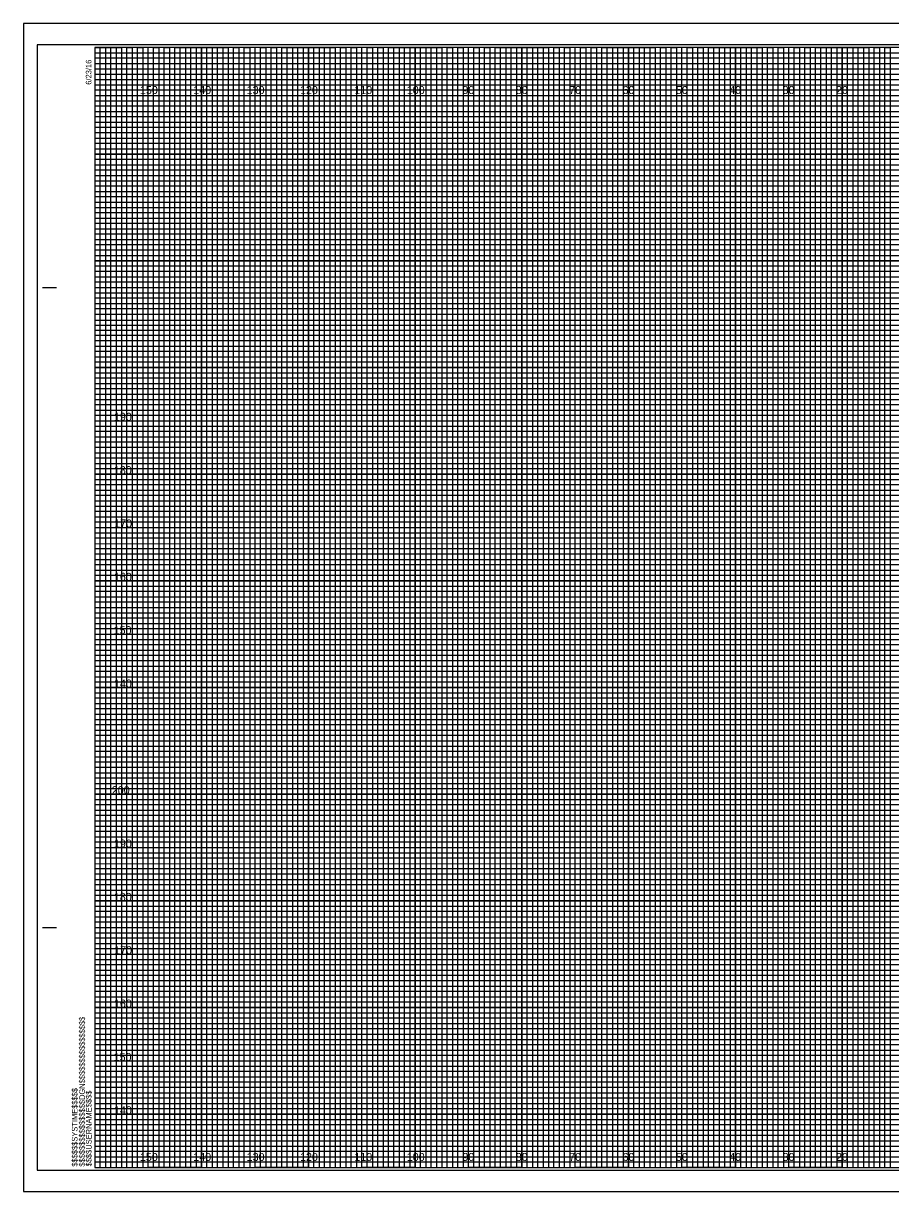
# Model space of a CAD drawing. Extents: x -13 to 323, y -5 to 4174.
# Drawn here: x -13.4 to 149.1, y 215.5 to 434.5 of the extents above; entities that cross this region are included whole.
import ezdxf

# ---------------------------------------------------------------- set-up
doc = ezdxf.new("R2010")
doc.units = 0
for name, color, linetype in [('Exist Cross Section Cell', 7, 'Continuous'), ('Exist XS Center Line Elevation Label', 7, 'Continuous'), ('Exist XS Ground Line', 7, 'Continuous'), ('Prop CMT Guardrail Graphics', 7, 'Continuous'), ('Prop CMT Pvmt Course 1', 7, 'Continuous'), ('Prop CMT Pvmt Course 2', 7, 'Continuous'), ('Prop CMT Pvmt Course 3', 7, 'Continuous'), ('Prop CMT Shld Paved Course 1', 7, 'Continuous'), ('Prop CMT Shld Paved Course 2', 7, 'Continuous'), ('Prop CMT Subgrade Earthwork', 7, 'Continuous'), ('Scratch_Level_0', 7, 'Continuous')]:
    doc.layers.add(name, color=color, linetype=linetype)

msp = doc.modelspace()

# ---------------------------------------------------------------- linework, layer by layer
at = {"layer": 'Exist XS Center Line Elevation Label'}
for points in [[(0, 430), (5, 430), (5, 220), (15, 220), (15, 430), (25, 430), (25, 220), (35, 220), (35, 430), (45, 430), (45, 220), (55, 220), (55, 430), (65, 430), (65, 220), (75, 220), (75, 430), (85, 430), (85, 220), (95, 220), (95, 430), (105, 430), (105, 220), (115, 220), (115, 430), (125, 430), (125, 220), (135, 220), (135, 430), (145, 430), (145, 220), (155, 220)], [(0, 425), (275, 425)], [(0, 405), (320, 405), (320, 415), (0, 415)], [(0, 385), (320, 385), (320, 395), (0, 395)], [(0, 365), (320, 365), (320, 375), (0, 375)], [(0, 345), (320, 345), (320, 355), (0, 355)], [(0, 325), (320, 325), (320, 335), (0, 335)], [(0, 305), (320, 305), (320, 315), (0, 315)], [(0, 285), (320, 285), (320, 295), (0, 295)], [(0, 265), (320, 265), (320, 275), (0, 275)], [(0, 245), (320, 245), (320, 255), (0, 255)], [(0, 225), (320, 225), (320, 235), (0, 235)]]:
    msp.add_lwpolyline(points, dxfattribs=at)
at = {"layer": 'Exist XS Ground Line'}
for p, q in [((10, 430), (0, 430)), ((10, 220), (10, 430)), ((30, 430), (20, 430)), ((20, 430), (20, 220)), ((30, 220), (30, 430)), ((50, 430), (40, 430)), ((40, 430), (40, 220)), ((50, 220), (50, 430)), ((70, 430), (60, 430)), ((60, 430), (60, 220)), ((70, 220), (70, 430)), ((90, 430), (80, 430)), ((80, 430), (80, 220)), ((90, 220), (90, 430)), ((110, 430), (100, 430)), ((100, 430), (100, 220)), ((110, 220), (110, 430)), ((130, 430), (120, 430)), ((120, 430), (120, 220)), ((130, 220), (130, 430)), ((150, 430), (140, 430)), ((140, 430), (140, 220)), ((20, 220), (10, 220)), ((40, 220), (30, 220)), ((60, 220), (50, 220)), ((80, 220), (70, 220)), ((100, 220), (90, 220)), ((120, 220), (110, 220)), ((140, 220), (130, 220))]:
    msp.add_line(p, q, dxfattribs=at)
for points in [[(0, 420), (320, 420), (320, 410), (0, 410)], [(0, 400), (320, 400), (320, 390), (0, 390)], [(0, 380), (320, 380), (320, 370), (0, 370)], [(0, 360), (320, 360), (320, 350), (0, 350)], [(0, 340), (320, 340), (320, 330), (0, 330)], [(0, 320), (320, 320), (320, 310), (0, 310)], [(0, 300), (320, 300), (320, 290), (0, 290)], [(0, 280), (320, 280), (320, 270), (0, 270)], [(0, 260), (320, 260), (320, 250), (0, 250)], [(0, 240), (320, 240), (320, 230), (0, 230)]]:
    msp.add_lwpolyline(points, dxfattribs=at)
at = {"layer": 'Prop CMT Pvmt Course 1'}
for p, q in [((323.3, 434.5), (-13.4, 434.5)), ((-13.4, 434.5), (-13.4, 215.5)), ((-13.4, 215.5), (323.3, 215.5))]:
    msp.add_line(p, q, dxfattribs=at)
at = {"layer": 'Prop CMT Pvmt Course 2'}
msp.add_lwpolyline([(-13.4, 215.5), (323.3, 215.5), (323.3, 434.5), (-13.4, 434.5)], close=True, dxfattribs=at)
at = {"layer": 'Prop CMT Pvmt Course 3'}
msp.add_lwpolyline([(-10.8, 219.5), (322.4, 219.5), (322.4, 430.5), (-10.8, 430.5)], close=True, dxfattribs=at)
at = {"layer": 'Prop CMT Shld Paved Course 1'}
for p, q in [((-9.8, 385), (-7.3, 385)), ((-9.7, 385), (-7.2, 385)), ((-9.8, 265), (-7.3, 265)), ((-9.7, 265), (-7.2, 265)), ((0, 220), (0, 220)), ((0, 220), (0, 220)), ((0, 220), (0, 220)), ((0, 220), (0, 220)), ((0, 220), (0, 220)), ((0, 220), (0, 220)), ((0, 220), (0, 220))]:
    msp.add_line(p, q, dxfattribs=at)
msp.add_lwpolyline([(320, 430), (0, 430), (0, 220), (320, 220)], close=True, dxfattribs=at)
at = {"layer": 'Prop CMT Shld Paved Course 2'}
for points in [[(0, 220), (1, 220), (1, 430), (2, 430), (2, 220)], [(2, 220), (3, 220), (3, 430), (4, 430), (4, 220)], [(5, 220), (6, 220), (6, 430), (7, 430), (7, 220)], [(7, 220), (8, 220), (8, 430), (9, 430), (9, 220)], [(10, 220), (11, 220), (11, 430), (12, 430), (12, 220)], [(12, 220), (13, 220), (13, 430), (14, 430), (14, 220)], [(15, 220), (16, 220), (16, 430), (17, 430), (17, 220)], [(17, 220), (18, 220), (18, 430), (19, 430), (19, 220)], [(20, 220), (21, 220), (21, 430), (22, 430), (22, 220)], [(22, 220), (23, 220), (23, 430), (24, 430), (24, 220)], [(25, 220), (26, 220), (26, 430), (27, 430), (27, 220)], [(27, 220), (28, 220), (28, 430), (29, 430), (29, 220)], [(30, 220), (31, 220), (31, 430), (32, 430), (32, 220)], [(32, 220), (33, 220), (33, 430), (34, 430), (34, 220)], [(35, 220), (36, 220), (36, 430), (37, 430), (37, 220)], [(37, 220), (38, 220), (38, 430), (39, 430), (39, 220)], [(40, 220), (41, 220), (41, 430), (42, 430), (42, 220)], [(42, 220), (43, 220), (43, 430), (44, 430), (44, 220)], [(45, 220), (46, 220), (46, 430), (47, 430), (47, 220)], [(47, 220), (48, 220), (48, 430), (49, 430), (49, 220)], [(50, 220), (51, 220), (51, 430), (52, 430), (52, 220)], [(52, 220), (53, 220), (53, 430), (54, 430), (54, 220)], [(55, 220), (56, 220), (56, 430), (57, 430), (57, 220)], [(57, 220), (58, 220), (58, 430), (59, 430), (59, 220)], [(60, 220), (61, 220), (61, 430), (62, 430), (62, 220)], [(62, 220), (63, 220), (63, 430), (64, 430), (64, 220)], [(65, 220), (66, 220), (66, 430), (67, 430), (67, 220)], [(67, 220), (68, 220), (68, 430), (69, 430), (69, 220)], [(70, 220), (71, 220), (71, 430), (72, 430), (72, 220)], [(72, 220), (73, 220), (73, 430), (74, 430), (74, 220)], [(75, 220), (76, 220), (76, 430), (77, 430), (77, 220)], [(77, 220), (78, 220), (78, 430), (79, 430), (79, 220)], [(80, 220), (81, 220), (81, 430), (82, 430), (82, 220)], [(82, 220), (83, 220), (83, 430), (84, 430), (84, 220)], [(85, 220), (86, 220), (86, 430), (87, 430), (87, 220)], [(87, 220), (88, 220), (88, 430), (89, 430), (89, 220)], [(90, 220), (91, 220), (91, 430), (92, 430), (92, 220)], [(92, 220), (93, 220), (93, 430), (94, 430), (94, 220)], [(95, 220), (96, 220), (96, 430), (97, 430), (97, 220)], [(97, 220), (98, 220), (98, 430), (99, 430), (99, 220)], [(100, 220), (101, 220), (101, 430), (102, 430), (102, 220)], [(102, 220), (103, 220), (103, 430), (104, 430), (104, 220)], [(105, 220), (106, 220), (106, 430), (107, 430), (107, 220)], [(107, 220), (108, 220), (108, 430), (109, 430), (109, 220)], [(110, 220), (111, 220), (111, 430), (112, 430), (112, 220)], [(112, 220), (113, 220), (113, 430), (114, 430), (114, 220)], [(115, 220), (116, 220), (116, 430), (117, 430), (117, 220)], [(117, 220), (118, 220), (118, 430), (119, 430), (119, 220)], [(120, 220), (121, 220), (121, 430), (122, 430), (122, 220)], [(122, 220), (123, 220), (123, 430), (124, 430), (124, 220)], [(125, 220), (126, 220), (126, 430), (127, 430), (127, 220)], [(127, 220), (128, 220), (128, 430), (129, 430), (129, 220)], [(130, 220), (131, 220), (131, 430), (132, 430), (132, 220)], [(132, 220), (133, 220), (133, 430), (134, 430), (134, 220)], [(135, 220), (136, 220), (136, 430), (137, 430), (137, 220)], [(137, 220), (138, 220), (138, 430), (139, 430), (139, 220)], [(140, 220), (141, 220), (141, 430), (142, 430), (142, 220)], [(142, 220), (143, 220), (143, 430), (144, 430), (144, 220)], [(145, 220), (146, 220), (146, 430), (147, 430), (147, 220)], [(147, 220), (148, 220), (148, 430), (149, 430), (149, 220)]]:
    msp.add_lwpolyline(points, dxfattribs=at)
at = {"layer": 'Prop CMT Subgrade Earthwork'}
for p, q in [((10, 220), (10, 430)), ((20, 220), (20, 430)), ((30, 220), (30, 430)), ((40, 220), (40, 430)), ((50, 220), (50, 430)), ((60, 220), (60, 430)), ((70, 220), (70, 430)), ((80, 220), (80, 430)), ((90, 220), (90, 430)), ((100, 220), (100, 430)), ((110, 220), (110, 430)), ((120, 220), (120, 430)), ((130, 220), (130, 430)), ((140, 220), (140, 430)), ((0, 420), (320, 420)), ((0, 410), (320, 410)), ((0, 400), (320, 400)), ((0, 390), (320, 390)), ((0, 380), (320, 380)), ((0, 370), (320, 370)), ((0, 360), (320, 360)), ((0, 350), (320, 350)), ((0, 340), (320, 340)), ((0, 330), (320, 330)), ((0, 320), (320, 320)), ((0, 310), (320, 310)), ((0, 300), (320, 300)), ((0, 290), (320, 290)), ((0, 280), (320, 280)), ((0, 270), (320, 270)), ((0, 260), (320, 260)), ((0, 250), (320, 250)), ((0, 240), (320, 240)), ((0, 230), (320, 230))]:
    msp.add_line(p, q, dxfattribs=at)
at = {"layer": 'Scratch_Level_0'}
for p, q in [((0, 429), (260, 429)), ((260, 427.98), (0, 427.98)), ((0, 427.98), (0, 427)), ((0, 427), (260, 427)), ((260, 425.89), (0, 425.89)), ((0, 425.89), (0, 424)), ((0, 424), (320, 424))]:
    msp.add_line(p, q, dxfattribs=at)
for points in [[(0, 423), (270, 423), (320, 423), (320, 422), (0, 422)], [(0, 421), (320, 421), (320, 419), (0, 419)], [(0, 418), (320, 418), (320, 417), (0, 416.98)], [(0, 416), (320, 416), (320, 414), (0, 414)], [(0, 413), (320, 413), (320, 412), (0, 412)], [(0, 411), (320, 411), (320, 409), (0, 409)], [(0, 408), (320, 408), (320, 407), (0, 407)], [(0, 406), (320, 406), (320, 404), (0, 404)], [(0, 403), (320, 403), (320, 402), (0, 402)], [(0, 401), (320, 401), (320, 399), (0, 399)], [(0, 398), (320, 398), (320, 397), (0, 397)], [(0, 396), (320, 396), (320, 393.95), (320, 393), (320, 392), (0, 392)], [(0, 394), (320, 394), (320, 393), (0, 393)], [(0, 391), (320, 391), (320, 389), (0, 389.03)], [(0, 389.03), (320, 389), (320, 388), (0, 388)], [(0, 387), (320, 387), (320, 386), (0, 386)], [(0, 384), (320, 384), (320, 383), (0, 383)], [(0, 382), (320, 382), (320, 381), (0, 381)], [(-0.07, 378.89), (320, 378.89), (320, 377.88), (-0.07, 377.88)], [(0, 377), (320, 377), (320, 376), (0, 376)], [(0, 374), (320, 374), (320, 373), (0, 373)], [(0, 372), (320, 372), (320, 371), (0, 371)], [(0, 369), (320, 369), (320, 368), (0, 368)], [(0, 367), (320, 367), (320, 366), (0, 366)], [(0, 364), (320, 364), (320, 363), (0, 363)], [(0, 362), (320, 362), (320, 361), (0, 361)], [(0, 359), (320, 359), (319.99, 357.98), (0, 358)], [(0, 357), (320, 357), (320, 356), (0, 356)], [(0, 354), (320, 354), (320, 353), (0, 353)], [(0, 352), (320, 352), (320, 351), (0, 351)], [(0, 349), (320, 349), (320, 348), (0, 348)], [(0, 347), (320, 347), (320, 346), (0, 346)], [(0, 344), (320, 344), (320, 343), (0, 343)], [(0, 342), (320, 342), (320, 341), (0, 341)], [(0, 339), (320, 339), (320, 338), (0, 338)], [(0, 336.99), (320.07, 336.91), (320, 336), (0, 336)], [(0, 334), (320, 334), (320, 333), (0, 333)], [(0, 332), (320, 332), (320, 331), (0, 331)], [(0, 329), (320, 329), (320, 328), (0, 328)], [(0, 327), (320, 327), (320, 326), (0, 326)], [(0, 324), (320, 324), (320, 323), (0, 323)], [(0, 322), (320, 322), (320, 321), (0, 321)], [(0, 319), (320, 319), (320, 318), (0, 318)], [(0, 317), (320, 317), (320, 316), (0, 316)], [(0, 314), (320, 314), (320, 313), (0, 313)], [(0, 312), (320, 312), (320, 311), (0, 311)], [(0, 309), (320, 309), (320, 308), (0, 308)], [(0, 307), (320, 307), (320, 306), (0, 306)], [(0, 304), (320, 304), (320, 303), (0, 303)], [(0, 302), (320, 302), (320, 301), (0, 301)], [(0, 299), (320, 299), (319.99, 297.98), (0, 298)], [(0, 297), (320, 297), (320, 296), (0, 296)], [(0, 294), (320, 294), (320, 293), (0, 293)], [(0, 292), (320, 292), (320, 291), (0, 291)], [(0, 289), (320, 289), (320, 288), (0, 288)], [(0, 287), (320, 287), (320, 286), (0, 286)], [(0, 284), (320, 284), (320, 283), (0, 283)], [(0, 282), (320, 282), (320, 281), (0, 281)], [(0, 279), (320, 279), (320, 278), (0, 278)], [(0, 276.99), (320.07, 276.91), (320, 276), (0, 276)], [(0, 274), (320, 274), (320, 273), (0, 273)], [(0, 272), (320, 272), (320, 271), (0, 271)], [(0, 269), (320, 269), (320, 268), (0, 268)], [(0, 267), (320, 267), (320, 266), (0, 266)], [(0, 264), (320, 264), (320, 263), (0, 263)], [(0, 262), (320, 262), (320, 261), (0, 261)], [(0, 259), (320, 259), (320, 258), (0, 258)], [(0, 257), (320, 257), (320, 256), (0, 256)], [(0, 254), (320, 254), (320, 253), (0, 253)], [(0, 252), (320, 252), (320, 251), (0, 251)], [(0, 249), (320, 249), (320, 248), (0, 248)], [(0, 247), (320, 247), (320, 246), (0, 246)], [(0, 244), (320, 244), (320, 243), (0, 243)], [(0, 242), (320, 242), (320, 241), (0, 241)], [(0, 239), (320, 239), (320, 238), (0, 238)], [(0, 237), (320, 237), (320, 236), (0, 236)], [(0, 234), (320, 234), (320, 233), (0, 233)], [(0, 232), (320, 232), (320, 231), (0, 231)], [(0, 229), (320, 229), (320, 228), (0, 228)], [(0, 227), (320, 227), (320, 226), (0, 226)], [(0, 224), (320, 224), (320, 223), (0, 223)], [(0, 222), (320, 222), (320, 221), (0, 221)]]:
    msp.add_lwpolyline(points, dxfattribs=at)

# ---------------------------------------------------------------- texts
at = {"layer": 'Exist Cross Section Cell'}
for s, p in [('150', (8.44, 421.25)), ('140', (18.44, 421.25)), ('130', (28.44, 421.25)), ('120', (38.44, 421.25)), ('110', (48.62, 421.25)), ('100', (58.44, 421.25)), ('90', (68.86, 421.25)), ('80', (78.86, 421.25)), ('70', (88.86, 421.25)), ('60', (98.86, 421.25)), ('50', (108.86, 421.25)), ('40', (118.86, 421.25)), ('30', (128.86, 421.25)), ('20', (138.86, 421.25)), ('150', (8.44, 221.25)), ('140', (18.44, 221.25)), ('130', (28.44, 221.25)), ('120', (38.44, 221.25)), ('110', (48.62, 221.25)), ('100', (58.44, 221.25)), ('90', (68.86, 221.25)), ('80', (78.86, 221.25)), ('70', (88.86, 221.25)), ('60', (98.86, 221.25)), ('50', (108.86, 221.25)), ('40', (118.86, 221.25)), ('30', (128.86, 221.25)), ('20', (138.86, 221.25))]:
    msp.add_text(s, height=1.5, dxfattribs=at).set_placement(p)
at = {"layer": 'Prop CMT Guardrail Graphics'}
for s, p in [('190', (3.57, 360)), ('180', (3.55, 350)), ('170', (3.61, 340)), ('160', (3.57, 330)), ('150', (3.52, 320)), ('140', (3.57, 310)), ('200', (3.17, 290)), ('190', (3.57, 280)), ('180', (3.55, 270)), ('170', (3.61, 260)), ('160', (3.57, 250)), ('150', (3.52, 240)), ('140', (3.57, 230))]:
    msp.add_text(s, height=1.5, dxfattribs=at).set_placement(p)
at = {"layer": 'Prop CMT Shld Paved Course 1'}
for s, p in [('6/23/16', (-0.65, 423)), ('$$$$$$$$$$$$$$$$DGN$$$$$$$$$$$$$$$$', (-1.88, 220.18)), ('$$$$$$SYSTIME$$$$$', (-3.26, 220.18)), ('$$$$USERNAME$$$$', (-0.62, 220.23))]:
    msp.add_text(s, height=1.05, rotation=90, dxfattribs=at).set_placement(p)

doc.saveas('drawing.dxf')
